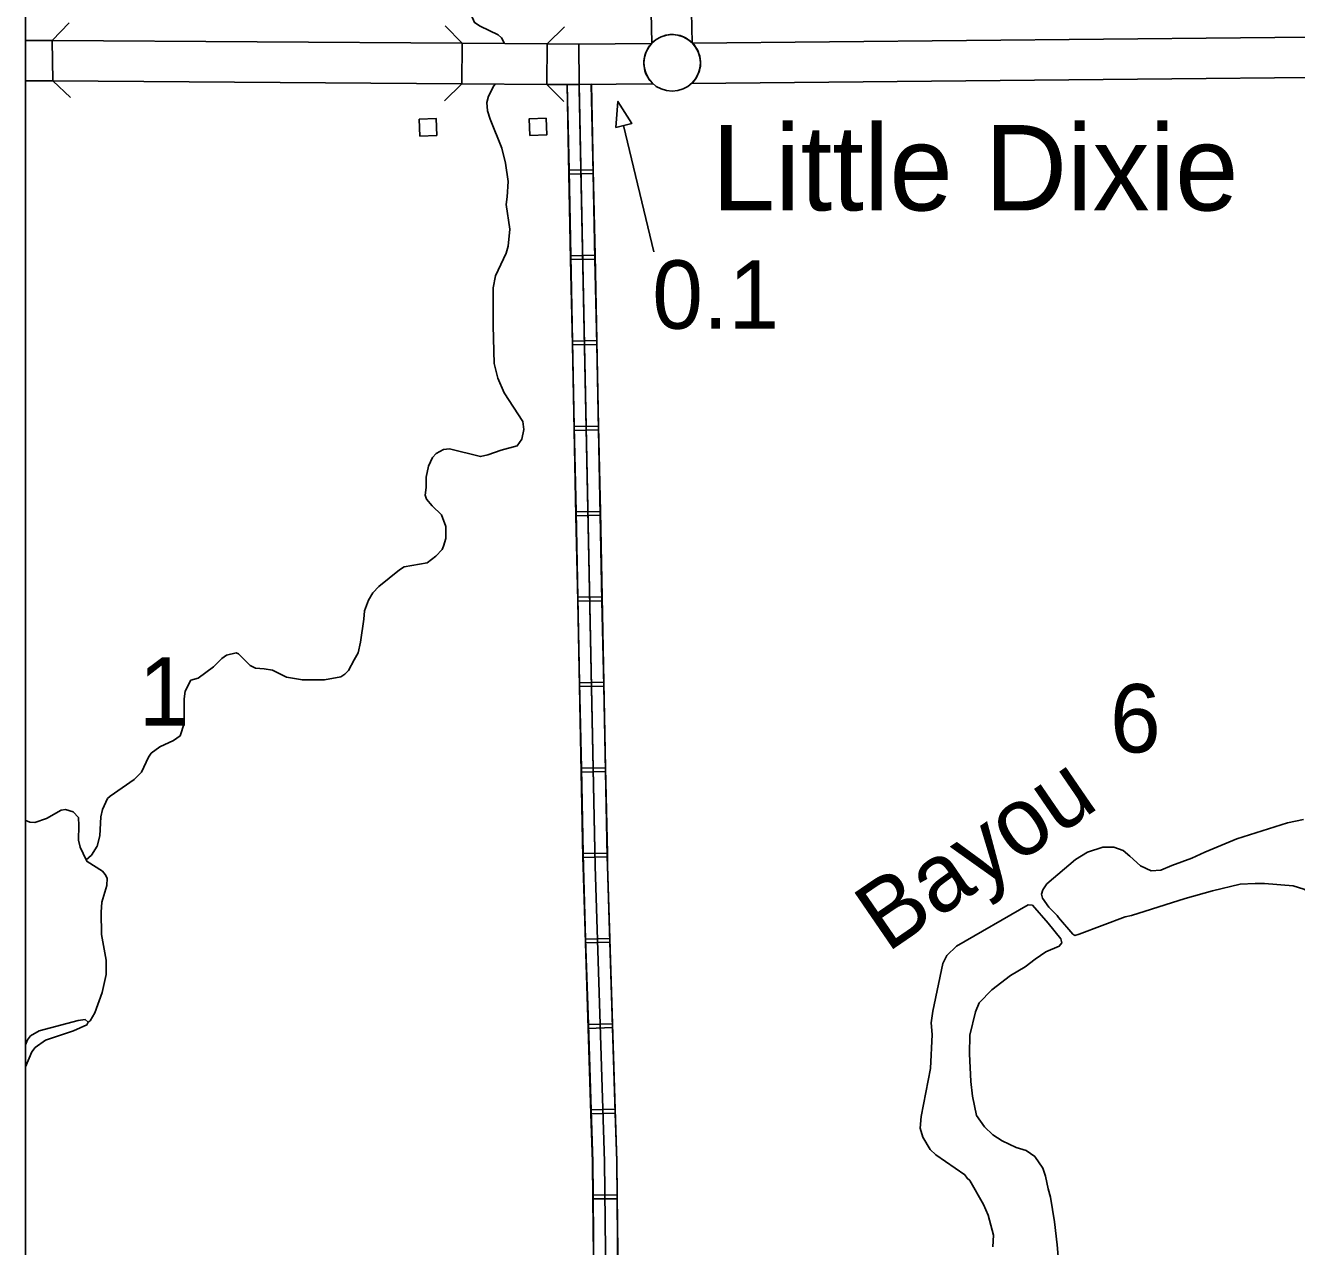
# Model space of a CAD drawing. Extents: x 1084508 to 1142749, y 1057638 to 1093403.
# Drawn here: x 1084508 to 1086974, y 1085312 to 1087680 of the extents above; entities that cross this region are included whole.
import ezdxf

# ---------------------------------------------------------------- set-up
doc = ezdxf.new("R2010")
doc.units = 0
for name, color, linetype in [('10', 7, 'Continuous'), ('24', 7, 'Continuous'), ('32', 7, 'Continuous'), ('35', 7, 'Continuous'), ('37', 7, 'Continuous'), ('5', 7, 'Continuous'), ('56', 7, 'Continuous'), ('DSN_DRFT_Named-Boundary', 7, 'Continuous'), ('Level 10', 7, 'Continuous'), ('Level 24', 7, 'Continuous'), ('Level 32', 7, 'Continuous'), ('Level 35', 7, 'Continuous'), ('Level 48', 7, 'Continuous'), ('Level 5', 7, 'Continuous'), ('Level 56', 7, 'Continuous')]:
    doc.layers.add(name, color=color, linetype=linetype)

msp = doc.modelspace()

# ---------------------------------------------------------------- linework, layer by layer
at = {"layer": '10'}
for p, q in [((1085797.5, 1087842), (1085801.5, 1087646.6)), ((1085723.1, 1087645.7), (1085719.1, 1087840.1)), ((1084507.9, 1087651.3), (1084559.9, 1087651.4)), ((1084561.4, 1087573), (1084559.9, 1087651.4)), ((1085355.3, 1087645.7), (1085354.7, 1087567.2)), ((1085355.3, 1087645.7), (1085520.3, 1087644.5)), ((1085519.6, 1087566), (1085520.3, 1087644.5)), ((1085581.6, 1087644.1), (1085722.9, 1087645.4)), ((1084561.4, 1087573), (1084507.9, 1087572.8)), ((1085519.6, 1087566), (1085354.7, 1087567.2)), ((1085725.8, 1087567), (1085582.3, 1087565.6))]:
    msp.add_line(p, q, dxfattribs=at)
for points in [[(1084559.9, 1087651.4), (1085355.3, 1087645.7)], [(1085520.3, 1087644.5), (1085581.6, 1087644.1)], [(1085722.9, 1087645.4), (1085720.5, 1087642.8), (1085718.7, 1087640.6), (1085717.3, 1087638.6), (1085715.4, 1087635.5), (1085714, 1087633), (1085712.3, 1087629.4), (1085711, 1087626.1), (1085709.8, 1087622.2), (1085709, 1087619), (1085708.4, 1087615.3), (1085707.9, 1087611.8), (1085707.8, 1087608.5), (1085707.9, 1087605.2), (1085708.2, 1087600.5), (1085709, 1087596.5), (1085710, 1087592), (1085711.3, 1087588.3), (1085712.6, 1087585.4), (1085713.7, 1087583), (1085715.3, 1087580.1), (1085716.8, 1087577.4), (1085719.4, 1087573.7), (1085722.4, 1087570.4), (1085724.3, 1087568.3), (1085725.8, 1087567)], [(1085801.5, 1087646.6), (1085800.2, 1087647.8), (1085798, 1087650), (1085795.4, 1087651.9), (1085791.9, 1087654.2), (1085788.7, 1087656.2), (1085784.6, 1087658.1), (1085781.7, 1087659.3), (1085778.2, 1087660.5), (1085773, 1087661.6), (1085769, 1087662.3), (1085765.6, 1087662.5), (1085761.8, 1087662.5), (1085758.2, 1087662.5), (1085754.8, 1087662), (1085750.6, 1087661.3), (1085745.1, 1087659.8), (1085741.4, 1087658.3), (1085737.4, 1087656.5), (1085732.8, 1087653.6), (1085729.1, 1087651), (1085725.9, 1087648.2), (1085723.1, 1087645.7)], [(1085582.3, 1087565.6), (1085581.6, 1087644.1)], [(1085581.6, 1087644.1), (1085582.3, 1087565.6)], [(1085354.7, 1087567.2), (1084561.4, 1087573)], [(1085582.3, 1087565.6), (1085519.6, 1087566)]]:
    msp.add_lwpolyline(points, dxfattribs=at)
at = {"layer": '24'}
msp.add_circle((1085762.7, 1087607.7), 54.9, dxfattribs=at)
at = {"layer": '32'}
for p, q in [((1085559.2, 1087565.1), (1085606.3, 1087566.1)), ((1085562.6, 1087399.4), (1085609.7, 1087400.4)), ((1085566.1, 1087233.7), (1085613.1, 1087234.7)), ((1085569.5, 1087068), (1085616.5, 1087069)), ((1085572.9, 1086902.3), (1085620, 1086903.3)), ((1085576.3, 1086736.7), (1085623.4, 1086737.6)), ((1085579.7, 1086571), (1085626.8, 1086571.9)), ((1085583.1, 1086405.3), (1085630.2, 1086406.2)), ((1085586.6, 1086239.6), (1085633.6, 1086240.5)), ((1085590, 1086073.9), (1085637.1, 1086074.8)), ((1085594.9, 1085908), (1085642, 1085909.5)), ((1085600.1, 1085742.3), (1085647.2, 1085743.8)), ((1085605.3, 1085576.7), (1085652.4, 1085578.2)), ((1085609.2, 1085411.5), (1085656.3, 1085412))]:
    msp.add_line(p, q, dxfattribs=at)
for points in [[(1085559.2, 1087565.1), (1085562.6, 1087399.4)], [(1085582.3, 1087565.6), (1085613.6, 1086049.7), (1085631.6, 1085476.8), (1085635.2, 1085132), (1085645.3, 1084315.2), (1085646.8, 1084296.3), (1085657.9, 1083480.1), (1085664.5, 1083458.3), (1085672.9, 1082993.9), (1085690.4, 1081819.2), (1085728.9, 1080137.4), (1085740.3, 1079480.5)], [(1085606.3, 1087566.1), (1085609.7, 1087400.4)], [(1085562.6, 1087399.4), (1085566.1, 1087233.7)], [(1085609.7, 1087400.4), (1085613.1, 1087234.7)], [(1085566.1, 1087233.7), (1085569.5, 1087068)], [(1085613.1, 1087234.7), (1085616.5, 1087069)], [(1085569.5, 1087068), (1085572.9, 1086902.3)], [(1085616.5, 1087069), (1085620, 1086903.3)], [(1085572.9, 1086902.3), (1085576.3, 1086736.7)], [(1085620, 1086903.3), (1085623.4, 1086737.6)], [(1085576.3, 1086736.7), (1085579.7, 1086571)], [(1085623.4, 1086737.6), (1085626.8, 1086571.9)], [(1085579.7, 1086571), (1085583.1, 1086405.3)], [(1085626.8, 1086571.9), (1085630.2, 1086406.2)], [(1085583.1, 1086405.3), (1085586.6, 1086239.6)], [(1085630.2, 1086406.2), (1085633.6, 1086240.5)], [(1085586.6, 1086239.6), (1085590, 1086073.9)], [(1085633.6, 1086240.5), (1085637.1, 1086074.8)], [(1085590, 1086073.9), (1085590.5, 1086049.1), (1085594.9, 1085908)], [(1085637.1, 1086074.8), (1085637.6, 1086050.3), (1085642, 1085909.5)], [(1085594.9, 1085908), (1085600.1, 1085742.3)], [(1085642, 1085909.5), (1085647.2, 1085743.8)], [(1085600.1, 1085742.3), (1085605.3, 1085576.7)], [(1085647.2, 1085743.8), (1085652.4, 1085578.2)], [(1085605.3, 1085576.7), (1085608.5, 1085476.3), (1085609.2, 1085411.5)], [(1085652.4, 1085578.2), (1085655.6, 1085477.3), (1085656.3, 1085412)], [(1085609.2, 1085411.5), (1085610.9, 1085245.8)], [(1085656.3, 1085412), (1085658, 1085246.3)]]:
    msp.add_lwpolyline(points, dxfattribs=at)
at = {"layer": '35'}
for points in [[(1085425.4, 1087661.9), (1085390.1, 1087678.6), (1085379.5, 1087686), (1085372.9, 1087700.9), (1085365.4, 1087755.3), (1085342.7, 1087803.7), (1085343, 1087811.9), (1085351.7, 1087830.4), (1085364, 1087840.4), (1085393.1, 1087853.5), (1085413.9, 1087868.8), (1085446.4, 1087900.1), (1085457.6, 1087904.7), (1085501.5, 1087903.5), (1085576.9, 1087906.4), (1085616.7, 1087913.2), (1085709.3, 1087918.5)], [(1085437.4, 1087645.1), (1085431.4, 1087656), (1085425.4, 1087661.9)], [(1085415.6, 1087097.4), (1085415.2, 1087171.4), (1085419.7, 1087194.6), (1085440.4, 1087238.8), (1085444.3, 1087252.4), (1085447.5, 1087285.4), (1085440.7, 1087333), (1085442.7, 1087347.9), (1085444.8, 1087377.3), (1085439.3, 1087413.3), (1085432.3, 1087442.3), (1085409.4, 1087498.2), (1085404.4, 1087514.4), (1085403.2, 1087530.7), (1085406.5, 1087543.4), (1085416.5, 1087563.3), (1085419.3, 1087566.7)], [(1085285.4, 1086784.2), (1085285.3, 1086804.3), (1085289.8, 1086825.6), (1085297.7, 1086842.3), (1085304.8, 1086850), (1085319.1, 1086857.5), (1085331, 1086858.9), (1085391, 1086844), (1085405.2, 1086847.2), (1085430.7, 1086856.7), (1085462.3, 1086864.7), (1085471.1, 1086878.1), (1085475, 1086896.5), (1085473.3, 1086912.2), (1085436.5, 1086967.4), (1085424.3, 1086996), (1085417.2, 1087024.4), (1085415.6, 1087097.4)], [(1085285.4, 1086784.2), (1085283.7, 1086769.2), (1085286, 1086761.4), (1085297.2, 1086748.7), (1085315, 1086730.9), (1085323.9, 1086708.2), (1085323.4, 1086684.9), (1085319.3, 1086670.2), (1085316.5, 1086663.7), (1085304.5, 1086650.9), (1085287.1, 1086638.1), (1085242.5, 1086630.1), (1085233.6, 1086624.6), (1085193.8, 1086591.9), (1085181.8, 1086580), (1085173.3, 1086565.7), (1085166.1, 1086544.6), (1085164.2, 1086528.6), (1085158.3, 1086483.8)], [(1085158.3, 1086483.8), (1085153.8, 1086463.3), (1085145.9, 1086450), (1085134.8, 1086429.3), (1085127.6, 1086421.7), (1085119.7, 1086416.6), (1085088.1, 1086411.1), (1085045.3, 1086410.7), (1085014.3, 1086416.2), (1084987.2, 1086429.5), (1084971.1, 1086432.6), (1084954, 1086433.4), (1084943.7, 1086438.9), (1084921.6, 1086461.5), (1084916.5, 1086463.2), (1084898.1, 1086458.9), (1084888.7, 1086452.5), (1084872.7, 1086436.3), (1084843.2, 1086414.4), (1084828.8, 1086410.1)], [(1084654.8, 1085960.1), (1084656.3, 1085979.7), (1084665.6, 1086011.9), (1084666.7, 1086026.1), (1084662.9, 1086033.6), (1084657.7, 1086039.7), (1084627.4, 1086058.5), (1084625.5, 1086061.5), (1084636.1, 1086071.1), (1084647.2, 1086088.1), (1084652.2, 1086108.2), (1084654.3, 1086145.4), (1084657.3, 1086159.4), (1084667.3, 1086180.6), (1084672.5, 1086185.5), (1084719.2, 1086217.7), (1084733.2, 1086232.1), (1084746.4, 1086261.2), (1084751.8, 1086268.7), (1084769, 1086281.3), (1084795, 1086293.5), (1084808.2, 1086302.5), (1084816.2, 1086326.1), (1084815.8, 1086374.3), (1084817.8, 1086389.2), (1084828.8, 1086410.1)], [(1084625.5, 1086061.5), (1084613.9, 1086086.7), (1084610.9, 1086100.1), (1084611.8, 1086128.5), (1084610.9, 1086143.9), (1084600.8, 1086155.2), (1084585.9, 1086159.4), (1084577.1, 1086158.2), (1084548.7, 1086141.7), (1084526, 1086134), (1084516.8, 1086134.9), (1084508.5, 1086138.4), (1084507.9, 1086138.9)], [(1084507.9, 1085660), (1084520.3, 1085689.7), (1084526.9, 1085698.1), (1084546.6, 1085711.7), (1084601, 1085730.1), (1084627.1, 1085742), (1084629.4, 1085747.1), (1084633.4, 1085749.5), (1084642.3, 1085765.2), (1084657, 1085804.5), (1084664.3, 1085839.5), (1084664.9, 1085866.9), (1084655.6, 1085917), (1084654.8, 1085960.1)], [(1084507.9, 1085703), (1084511.9, 1085712.7), (1084517.9, 1085720.5), (1084534.9, 1085729.9), (1084610.4, 1085750.2), (1084623.6, 1085752.3), (1084629.4, 1085747.1)]]:
    msp.add_lwpolyline(points, dxfattribs=at)
at = {"layer": '37'}
for points in [[(1084559.9, 1087651.4), (1084592.6, 1087685.4)], [(1085322.3, 1087679.3), (1085355.3, 1087645.7)], [(1085520.3, 1087644.5), (1085553.8, 1087677.5)], [(1084595.3, 1087540.3), (1084561.4, 1087573)], [(1085354.7, 1087567.2), (1085321.1, 1087534.2)], [(1085552.6, 1087532.5), (1085519.6, 1087566)]]:
    msp.add_lwpolyline(points, dxfattribs=at)
at = {"layer": '56'}
for points in [[(1085273.3, 1087465.7), (1085272.1, 1087498.3), (1085304.9, 1087499.5), (1085306.1, 1087466.9)], [(1085486.6, 1087466.6), (1085485.4, 1087499.2), (1085518.1, 1087500.4), (1085519.3, 1087467.8)]]:
    msp.add_lwpolyline(points, close=True, dxfattribs=at)
at = {"layer": 'DSN_DRFT_Named-Boundary'}
msp.add_lwpolyline([(1084507.9, 1057640), (1142749.2, 1057640), (1142749.2, 1093403.4), (1084507.9, 1093403.4)], close=True, dxfattribs=at)
at = {"layer": 'Level 10'}
for p, q in [((1085797.5, 1087842), (1085801.5, 1087646.6)), ((1085723.1, 1087645.7), (1085719.1, 1087840.1)), ((1085581.6, 1087644.1), (1085722.9, 1087645.4)), ((1085725.8, 1087567), (1085582.3, 1087565.6))]:
    msp.add_line(p, q, dxfattribs=at)
for points in [[(1085801.9, 1087646.2), (1087928.8, 1087666.8), (1088091.3, 1087669.7)], [(1085722.9, 1087645.4), (1085720.5, 1087642.8), (1085718.7, 1087640.6), (1085717.3, 1087638.6), (1085715.4, 1087635.5), (1085714, 1087633), (1085712.3, 1087629.4), (1085711, 1087626.1), (1085709.8, 1087622.2), (1085709, 1087619), (1085708.4, 1087615.3), (1085707.9, 1087611.8), (1085707.8, 1087608.5), (1085707.9, 1087605.2), (1085708.2, 1087600.5), (1085709, 1087596.5), (1085710, 1087592), (1085711.3, 1087588.3), (1085712.6, 1087585.4), (1085713.7, 1087583), (1085715.3, 1087580.1), (1085716.8, 1087577.4), (1085719.4, 1087573.7), (1085722.4, 1087570.4), (1085724.3, 1087568.3), (1085725.8, 1087567)], [(1085801.5, 1087646.6), (1085800.2, 1087647.8), (1085798, 1087650), (1085795.4, 1087651.9), (1085791.9, 1087654.2), (1085788.7, 1087656.2), (1085784.6, 1087658.1), (1085781.7, 1087659.3), (1085778.2, 1087660.5), (1085773, 1087661.6), (1085769, 1087662.3), (1085765.6, 1087662.5), (1085761.8, 1087662.5), (1085758.2, 1087662.5), (1085754.8, 1087662), (1085750.6, 1087661.3), (1085745.1, 1087659.8), (1085741.4, 1087658.3), (1085737.4, 1087656.5), (1085732.8, 1087653.6), (1085729.1, 1087651), (1085725.9, 1087648.2), (1085723.1, 1087645.7)], [(1085800.4, 1087567.7), (1085801.9, 1087569.1), (1085804.7, 1087572.1), (1085807.3, 1087575.5), (1085810.1, 1087579.4), (1085812.2, 1087584.1), (1085814.5, 1087588.7), (1085815.6, 1087592.9), (1085816.5, 1087596.9), (1085817.4, 1087601.2), (1085817.5, 1087605.3), (1085817.6, 1087610.5), (1085817.1, 1087615.8), (1085816.2, 1087620.7), (1085814.8, 1087625.3), (1085813.2, 1087629.5), (1085811.6, 1087633.1), (1085808.8, 1087637.4), (1085807, 1087640.5), (1085804.5, 1087643.7), (1085801.9, 1087646.2)], [(1085582.3, 1087565.6), (1085581.6, 1087644.1)], [(1088092.5, 1087591.3), (1087929.9, 1087588.3), (1085800.4, 1087567.7)]]:
    msp.add_lwpolyline(points, dxfattribs=at)
at = {"layer": 'Level 24'}
msp.add_circle((1085762.7, 1087607.7), 54.9, dxfattribs=at)
at = {"layer": 'Level 32'}
for p, q in [((1085562.4, 1087391.9), (1085609.4, 1087392.9)), ((1085565.8, 1087226.3), (1085612.8, 1087227.2)), ((1085569.2, 1087060.6), (1085616.3, 1087061.5)), ((1085572.6, 1086894.9), (1085619.7, 1086895.8)), ((1085576, 1086729.2), (1085623.1, 1086730.1)), ((1085579.4, 1086563.5), (1085626.5, 1086564.4)), ((1085582.9, 1086397.8), (1085629.9, 1086398.7)), ((1085586.3, 1086232.1), (1085633.4, 1086233.1)), ((1085589.7, 1086066.4), (1085636.8, 1086067.4)), ((1085594.7, 1085900.5), (1085641.8, 1085902)), ((1085599.9, 1085734.8), (1085647, 1085736.3)), ((1085605.1, 1085569.2), (1085652.2, 1085570.7)), ((1085608.8, 1085404), (1085655.9, 1085404.5))]:
    msp.add_line(p, q, dxfattribs=at)
for points in [[(1085558.8, 1087565.4), (1085562.4, 1087391.9)], [(1085582.5, 1087558.1), (1085613.6, 1086049.7), (1085631.6, 1085476.8), (1085635.2, 1085132), (1085645.3, 1084315.2), (1085646.8, 1084296.3), (1085657.9, 1083480.1), (1085664.5, 1083458.3), (1085672.9, 1082993.9), (1085690.4, 1081819.2), (1085728.9, 1080137.4), (1085740.3, 1079480.5)], [(1085605.9, 1087565.8), (1085609.4, 1087392.9)], [(1085562.4, 1087391.9), (1085565.8, 1087226.3)], [(1085609.4, 1087392.9), (1085612.8, 1087227.2)], [(1085565.8, 1087226.3), (1085569.2, 1087060.6)], [(1085612.8, 1087227.2), (1085616.3, 1087061.5)], [(1085569.2, 1087060.6), (1085572.6, 1086894.9)], [(1085616.3, 1087061.5), (1085619.7, 1086895.8)], [(1085572.6, 1086894.9), (1085576, 1086729.2)], [(1085619.7, 1086895.8), (1085623.1, 1086730.1)], [(1085576, 1086729.2), (1085579.4, 1086563.5)], [(1085623.1, 1086730.1), (1085626.5, 1086564.4)], [(1085579.4, 1086563.5), (1085582.9, 1086397.8)], [(1085626.5, 1086564.4), (1085629.9, 1086398.7)], [(1085582.9, 1086397.8), (1085586.3, 1086232.1)], [(1085629.9, 1086398.7), (1085633.4, 1086233.1)], [(1085586.3, 1086232.1), (1085589.7, 1086066.4)], [(1085633.4, 1086233.1), (1085636.8, 1086067.4)], [(1085589.7, 1086066.4), (1085590.1, 1086049.1), (1085594.7, 1085900.5)], [(1085636.8, 1086067.4), (1085637.1, 1086050.3), (1085641.8, 1085902)], [(1085594.7, 1085900.5), (1085599.9, 1085734.8)], [(1085641.8, 1085902), (1085647, 1085736.3)], [(1085599.9, 1085734.8), (1085605.1, 1085569.2)], [(1085647, 1085736.3), (1085652.2, 1085570.7)], [(1085605.1, 1085569.2), (1085608.1, 1085476.3), (1085608.8, 1085404)], [(1085652.2, 1085570.7), (1085655.1, 1085477.3), (1085655.9, 1085404.5)], [(1085608.8, 1085404), (1085610.6, 1085238.3)], [(1085655.9, 1085404.5), (1085657.6, 1085238.8)]]:
    msp.add_lwpolyline(points, dxfattribs=at)
at = {"layer": 'Level 35'}
for points in [[(1086987.6, 1086140.2), (1086956.8, 1086133.4), (1086858.4, 1086102.4), (1086796, 1086076.8), (1086770.8, 1086065.2), (1086732.4, 1086051.1), (1086711.1, 1086042), (1086692.3, 1086040.5), (1086671.1, 1086050.2), (1086650.7, 1086069.2), (1086637.9, 1086079.9), (1086619.7, 1086086.7), (1086598.6, 1086086.3), (1086568.3, 1086076.4), (1086545.3, 1086062.7), (1086489.9, 1086015.1), (1086481.6, 1086003.3), (1086479.4, 1085995), (1086481, 1085987.2), (1086493.8, 1085969.8), (1086509.9, 1085953.8), (1086512.6, 1085950.2)], [(1086512.6, 1085950.2), (1086540.2, 1085917.7), (1086543.8, 1085915.3), (1086552.5, 1085917.6), (1086641.6, 1085951), (1086653.7, 1085953.8), (1086758.3, 1085986.7), (1086810.8, 1086001.7), (1086864.9, 1086014.3), (1086894.1, 1086016), (1086911.7, 1086015.8), (1086967.6, 1086011.1), (1086988.4, 1086005.1), (1087015.8, 1085990), (1087042.7, 1085966.3), (1087060.1, 1085955.7), (1087075.7, 1085952.6), (1087093.8, 1085956.3), (1087114.4, 1085965.5), (1087126.1, 1085978.9), (1087134.9, 1086000.2), (1087131.6, 1086039.5)], [(1086492.3, 1085938.8), (1086461.8, 1085974), (1086453.3, 1085974.6), (1086314.4, 1085894.1), (1086295.4, 1085876.1), (1086288.2, 1085861), (1086268.5, 1085768.2), (1086265.4, 1085745.7), (1086267.4, 1085722.8), (1086264.1, 1085657), (1086245.9, 1085563.7), (1086244.1, 1085541.5), (1086249, 1085523.7), (1086263, 1085499.8), (1086274.1, 1085489.9), (1086330.3, 1085450.5), (1086335, 1085444.1), (1086340.6, 1085439.6), (1086366.9, 1085393.1), (1086375.7, 1085372.4), (1086385.9, 1085334), (1086385.1, 1085311)], [(1086467.2, 1085868.9), (1086487.9, 1085883.1), (1086513.9, 1085894.1), (1086518.9, 1085900.9), (1086517, 1085908.4), (1086492.3, 1085938.8)], [(1086513.1, 1085277.1), (1086509.8, 1085315.1), (1086504.4, 1085359.4), (1086496.5, 1085407.6), (1086492, 1085423.8), (1086487.4, 1085448.2), (1086482, 1085463.7), (1086466.5, 1085486.1), (1086449.9, 1085498.2), (1086430.5, 1085504), (1086403.2, 1085516.9), (1086384.7, 1085528.7), (1086368.6, 1085544), (1086353.1, 1085565.7), (1086345.4, 1085603.6), (1086342.3, 1085632.1), (1086339.6, 1085685.4), (1086340.4, 1085722), (1086351, 1085767), (1086358.4, 1085784.7), (1086382.7, 1085809.5), (1086419.2, 1085837.6), (1086447.4, 1085854.1), (1086467.2, 1085868.9)]]:
    msp.add_lwpolyline(points, dxfattribs=at)
at = {"layer": 'Level 48'}
msp.add_line((1085668.1, 1087486), (1085727.1, 1087241.4), dxfattribs=at)
at = {"layer": 'Level 56'}
msp.add_lwpolyline([(1085653.3, 1087482.4), (1085684.4, 1087490), (1085657.6, 1087532.9)], close=True, dxfattribs=at)

# ---------------------------------------------------------------- texts
at = {"layer": '5'}
msp.add_text('1', height=132.6, dxfattribs=at).set_placement((1084727.6, 1086322.3))
at = {"layer": 'Level 24'}
msp.add_text('Little Dixie', height=165.73, dxfattribs=at).set_placement((1085839.3, 1087321.4))
at = {"layer": 'Level 35'}
msp.add_text('Bayou', height=132.58, rotation=34.4234, dxfattribs=at).set_placement((1086179.6, 1085880.5))
at = {"layer": 'Level 48'}
msp.add_text('0.1', height=132.58, dxfattribs=at).set_placement((1085724, 1087092))
at = {"layer": 'Level 5'}
msp.add_text('6', height=132.6, dxfattribs=at).set_placement((1086612.2, 1086270.1))

doc.saveas('drawing.dxf')
